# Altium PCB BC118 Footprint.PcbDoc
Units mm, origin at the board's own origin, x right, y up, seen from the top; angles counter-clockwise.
Board outline 152.4 x 101.6 mm, 2 copper layers (Top Layer, Bottom Layer); 0 components, 0 nets, 35 pads, 0 vias.
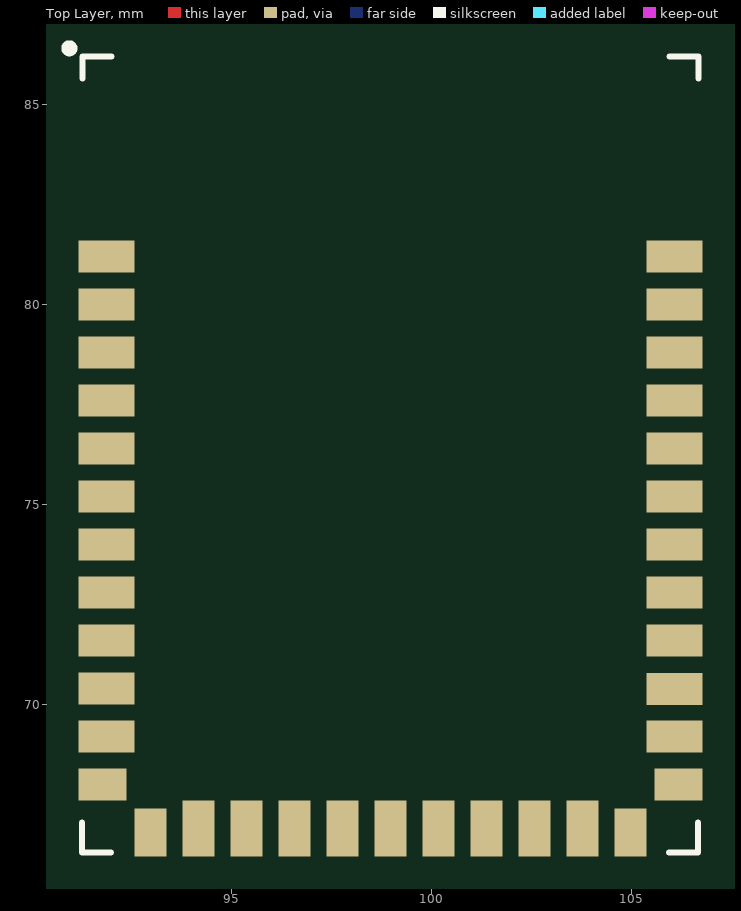
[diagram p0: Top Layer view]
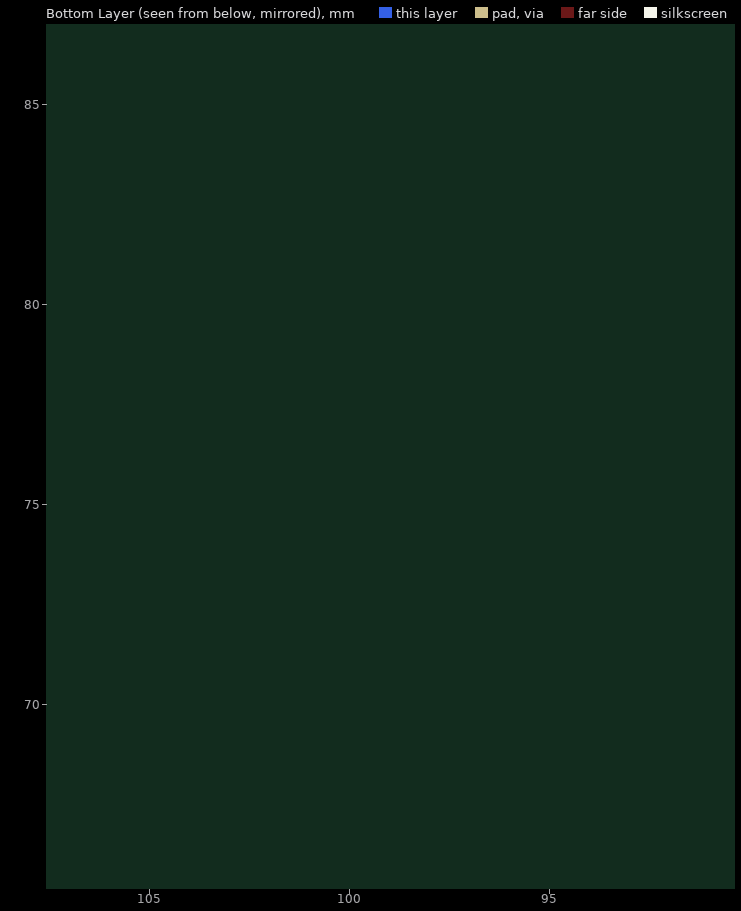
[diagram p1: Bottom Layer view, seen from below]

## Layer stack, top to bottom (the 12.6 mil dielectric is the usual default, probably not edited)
Top Solder: solder mask 0.0102, Solder Resist, Dk 3.5
Top Layer: signal copper 0.0356
Dielectric 1: dielectric 0.32, FR-4, Dk 4.8
Bottom Layer: signal copper 0.0356
Bottom Solder: solder mask 0.0102, Solder Resist, Dk 3.5

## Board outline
25.4,25.4 177.8,25.4 177.8,127 25.4,127

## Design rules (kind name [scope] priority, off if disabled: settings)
Clearance [All] p1: gap=0.254
PolygonConnect [All] p1: connectstyle=Relief reliefconductorwidth=0.254 reliefentries=4 polygonreliefangle="90 Angle" airgapwidth=0.254
RoutingVias [All] p1: holewidth=0.711 width=1.27 viastyle="Through Hole" minholewidth=0.711 minwidth=1.27 maxholewidth=0.711 maxwidth=1.27
SolderMaskExpansion [All] p1: expansion=0.102
Width [All] p1: maxlimit=0.254 minlimit=0.254 preferedwidth=0.254
29 further rules are at their usual default settings.

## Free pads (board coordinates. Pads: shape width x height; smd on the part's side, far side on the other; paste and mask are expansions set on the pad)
  rect 1.4x0.8 smd paste+0: 1(91.878,81.211) 2(91.878,80.011) 3(91.878,78.811) 4(91.878,77.611) 5(91.878,76.411) 6(91.878,75.211) 7(91.878,74.011) 8(91.878,72.811) 9(91.878,71.611) 10(91.878,70.411) 11(91.878,69.211) 25(106.078,69.211) 26(106.078,70.391) 30(106.078,75.211) 31(106.078,76.411) 32(106.078,77.611) 33(106.078,78.811) 34(106.078,80.011) 35(106.078,81.211)
  rect 1.2x0.8 smd paste+0: 12(91.778,68.011) 24(106.178,68.011)
  rect 0.8x1.2 smd paste+0: 13(92.978,66.811) 23(104.978,66.811)
  rect 0.8x1.4 smd paste+0: 14(94.178,66.911) 15(95.378,66.911) 16(96.578,66.911) 17(97.778,66.911) 18(98.978,66.911) 19(100.178,66.911) 20(101.378,66.911) 21(102.578,66.911) 22(103.778,66.911)
  rect 1.4x0.8 smd: 27(106.078,71.611) 28(106.078,72.811) 29(106.078,74.011)

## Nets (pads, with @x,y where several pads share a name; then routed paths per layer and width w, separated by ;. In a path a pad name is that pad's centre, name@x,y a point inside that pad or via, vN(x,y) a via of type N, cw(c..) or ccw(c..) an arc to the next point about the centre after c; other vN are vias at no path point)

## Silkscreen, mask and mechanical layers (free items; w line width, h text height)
Top Overlay:
  circle w0.2: c90.953,86.411 r0.1
  lines w0.15: 91.268,67.061 91.268,66.311 91.993,66.311 ; 91.278,85.661 91.278,86.211 92.003,86.211 ; 105.948,66.311 106.673,66.311 106.673,67.061 ; 105.953,86.211 106.678,86.211 106.678,85.661
Mechanical 4:
  circle w0.1: c92.378,85.181 r0.3
  lines w0.1: 91.778,81.801 106.178,81.801
  lines w0.15: 91.778,66.811 91.778,85.711 106.178,85.711 106.178,66.811 91.778,66.811
  text "GND Cut Out" at 95.058,83.121 h0.8
  text ".Designator" at 98.978,76.261 h0.6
